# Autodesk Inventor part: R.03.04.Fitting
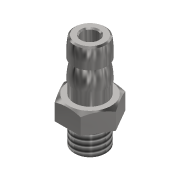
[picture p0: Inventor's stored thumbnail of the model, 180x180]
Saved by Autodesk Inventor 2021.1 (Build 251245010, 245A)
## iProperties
Created: 2021-02
Part Number: R.03.04.Fitting
Material: Stainless Steel
Document SubType Name: Modeling
Designer: Михальчик
Density: 8 g/cm^3
Appearance: Semi-Polished
Author: Михальчик
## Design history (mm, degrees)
sketch "Sketch1"
  geometry: L1 (0, 0)-(17.073, 0); L2 (0, 0)-(15, 0); L3 (15, 0)-(15, -1.25); L4 (15, -1.25)-(0, -1.25); L5 (0, -1.25)-(0, 0); L6 (0, 0)-(4, 0); L7 (4, 0)-(4, -2.5); L8 (4, -2.5)-(0, -2.5); L9 (0, -2.5)-(0, 0); L10 (4, 0)-(7, 0); L11 (7, 0)-(7, -4.3); L12 (7, -4.3)-(4, -4.3); L13 (4, -4.3)-(4, 0); L14 (7, -3.3)-(6.423, -4.3); L15 (7, -3.3)-(8.155, -3.3); L16 (7, 0)-(9, 0); L17 (9, 0)-(9, -2.5); L18 (9, -2.5)-(7, -2.5); L19 (7, -2.5)-(7, 0); L20 (9, -2.5)-(9, -2.625); L21 (12, -2.164)-(12, -2.625); L22 (12, -2.625)-(13, -2.625); L23 (15, -2.423)-(15, -1.25); A1 r 10 centre (9, 7.375) between (9, -2.625) and (12, -2.164); A2 r 10 centre (13, 7.375) between (13, -2.625) and (15, -2.423); 3 further points
  constraints: 46 end point, 9 parallel, 6 horizontal, 6 perpendicular, 5 point on line, 4 point on circle, 2 centre point, 1 collinear, 1 equal length, 1 equal radius, 1 tangent, 1 vertical
  dimensions: "d0" = 15 distance of L3.end L4.end; "d1" = 2.5 diameter of L4 L1; "d2" = 4 distance of L7.end L8.end; "d3" = 2.5 distance of L6.end L7.end; "d4" = 3 distance of L11.end L12.end; "d5" = 4.3 distance of L10.end L11.end; "d6" = 120 deg angle of L14 L15; "d7" = 1 vertical distance of L14.start L14.end; "d8" = 2 distance of L17.end L18.end; "d9" = 2.5 distance of L16.end L17.end; "d10" = 5.25 diameter of L22 L1; "d11" = 3 distance between parallel lines of L17 L21; "d12" = 10 radius of A1; "d13" = 1 distance of L21.end L22.end
revolve "Revolution1" sketch "Sketch1" stored, may be unused: angle "d14" = 90 deg
chamfer "Chamfer1" distance "d15" = 0.2; stored, may be unused: second distance "d16" = 2, angle "d17" = 45 deg
thread "Thread1" dims "d18" = 3.8, "d19" = 0
sketch "Sketch2"
  geometry: L1 (-4.041, 0)-(-2.021, 3.5); L2 (-2.021, 3.5)-(2.021, 3.5); L3 (2.021, 3.5)-(4.041, 0); L4 (4.041, 0)-(2.021, -3.5); L5 (2.021, -3.5)-(-2.021, -3.5); L6 (-2.021, -3.5)-(-4.041, 0); C1 r 4.3 at (0, 0); C2 r 4.3 at (0, 0) reference; 2 further points
  constraints: 12 end point, 2 coincident, 1 centre point, 1 concentric, 1 horizontal, 13 other
  dimensions: "d20" = 7 distance between parallel lines of L2 L5
extrude "Extrusion1" cut sketch "Sketch2" distance "d21" = 10; taper "d22" = 0 deg
body "Solid1"
